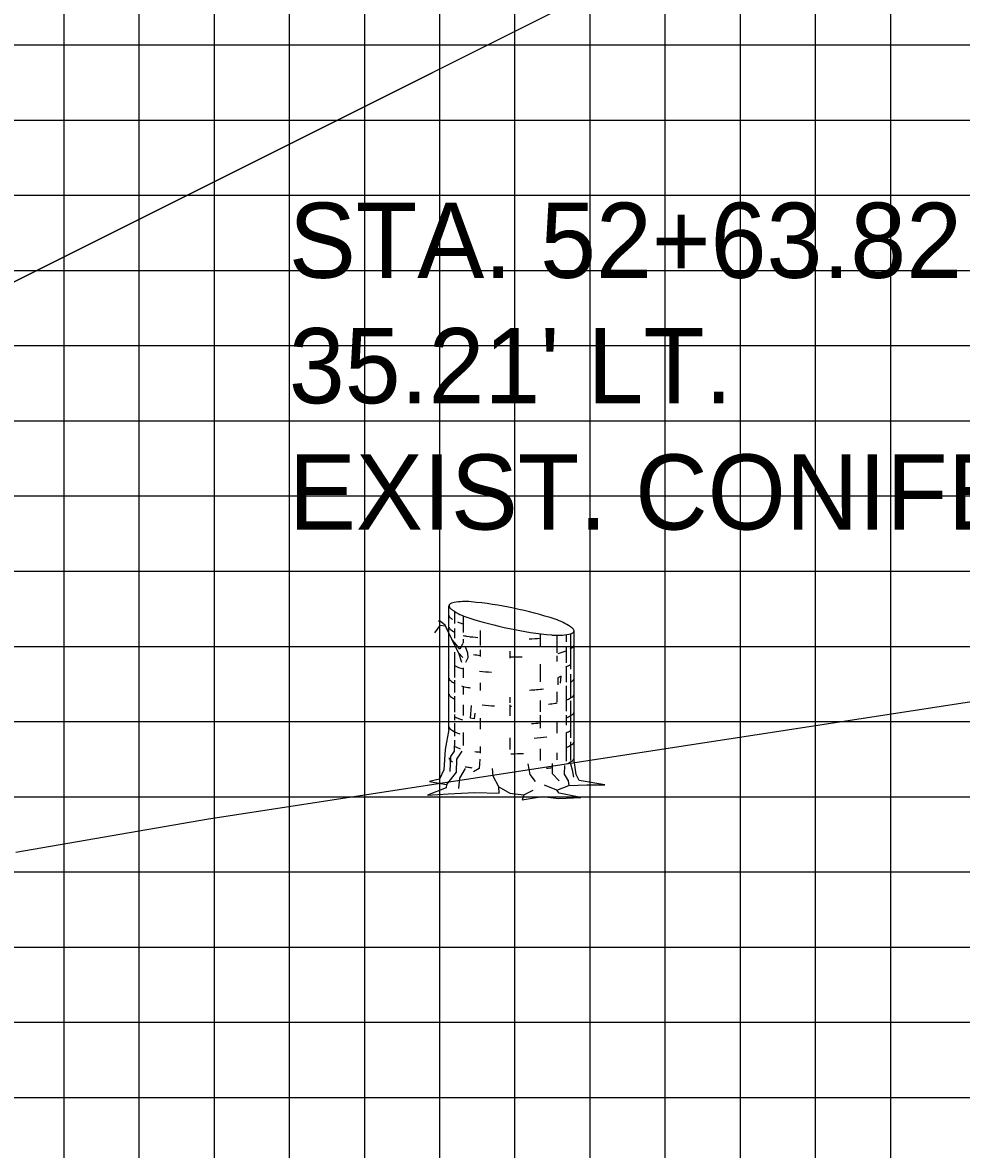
# Model space of a CAD drawing. Extents: x 1755888 to 1756232, y 442591 to 442811.
# Drawn here: x 1756011.5 to 1756024, y 442675.97 to 442690.96 of the extents above; entities that cross this region are included whole.
import ezdxf

# ---------------------------------------------------------------- set-up
doc = ezdxf.new("R2010")
doc.units = 0
for name, color, linetype in [('D_Roadway_Centerline', 7, 'Continuous'), ('D_Roadway_SlopeLines', 7, 'Continuous'), ('D_Text_Monospaced', 7, 'Continuous'), ('M_Trees_Conifer_Pay', 7, 'Continuous'), ('MAJOR', 7, 'Continuous'), ('MINOR', 7, 'Continuous'), ('S_Roadway_Centerline', 7, 'Continuous')]:
    doc.layers.add(name, color=color, linetype=linetype)

msp = doc.modelspace()

# ---------------------------------------------------------------- linework, layer by layer
at = {"layer": 'D_Roadway_Centerline'}
msp.add_lwpolyline([(1755988.922, 442676.281), (1756026.307, 442694.973), (1756031.057, 442697.348), (1756034.057, 442697.468), (1756042.057, 442697.788), (1756054.057, 442698.028), (1756066.057, 442697.788), (1756078.057, 442697.314), (1756093.723, 442696.688), (1756103.154, 442694.068), (1756119.307, 442689.581)], dxfattribs=at)
at = {"layer": 'D_Roadway_SlopeLines'}
msp.add_lwpolyline([(1756031.057, 442697.348), (1755988.922, 442676.281)], dxfattribs=at)
at = {"layer": 'M_Trees_Conifer_Pay'}
for p, q in [((1756017.179, 442681.557), (1756017.179, 442683.204)), ((1756017.251, 442683.132), (1756017.251, 442682.969)), ((1756017.368, 442683.071), (1756017.368, 442682.848)), ((1756017.251, 442682.902), (1756017.251, 442682.774)), ((1756017.596, 442682.875), (1756017.596, 442682.675)), ((1756017.368, 442682.759), (1756017.368, 442682.712)), ((1756018.392, 442682.833), (1756018.392, 442682.665)), ((1756018.612, 442682.813), (1756018.612, 442682.58)), ((1756018.737, 442682.82), (1756018.737, 442682.723)), ((1756018.796, 442682.832), (1756018.796, 442682.36)), ((1756018.843, 442681.147), (1756018.843, 442682.869)), ((1756017.251, 442682.587), (1756017.251, 442682.251)), ((1756017.311, 442682.576), (1756017.362, 442682.517)), ((1756017.596, 442682.618), (1756017.596, 442682.529)), ((1756017.987, 442682.601), (1756017.987, 442682.506)), ((1756018.737, 442682.648), (1756018.737, 442682.444)), ((1756018.392, 442682.428), (1756018.392, 442682.191)), ((1756018.612, 442682.54), (1756018.612, 442682.465)), ((1756017.368, 442682.377), (1756017.368, 442682.245)), ((1756018.737, 442682.387), (1756018.737, 442682.187)), ((1756018.796, 442682.296), (1756018.796, 442681.988)), ((1756017.251, 442682.214), (1756017.251, 442682.051)), ((1756017.368, 442682.134), (1756017.368, 442682.024)), ((1756017.596, 442682.181), (1756017.596, 442682.076)), ((1756018.737, 442682.14), (1756018.737, 442681.804)), ((1756017.251, 442682.004), (1756017.251, 442681.788)), ((1756017.987, 442681.988), (1756017.987, 442681.914)), ((1756018.612, 442682.062), (1756018.612, 442681.923)), ((1756017.368, 442681.889), (1756017.368, 442681.747)), ((1756017.987, 442681.889), (1756017.987, 442681.74)), ((1756018.392, 442681.946), (1756018.392, 442681.794)), ((1756018.796, 442681.94), (1756018.796, 442681.448)), ((1756017.251, 442681.757), (1756017.251, 442681.683)), ((1756017.596, 442681.709), (1756017.596, 442681.563)), ((1756018.392, 442681.751), (1756018.392, 442681.578)), ((1756018.737, 442681.751), (1756018.737, 442681.615)), ((1756017.251, 442681.642), (1756017.251, 442681.469)), ((1756018.612, 442681.652), (1756018.612, 442681.51)), ((1756017.368, 442681.52), (1756017.368, 442681.347)), ((1756017.987, 442681.448), (1756017.987, 442681.295)), ((1756018.737, 442681.516), (1756018.737, 442681.137)), ((1756018.796, 442681.395), (1756018.796, 442681.147)), ((1756017.596, 442681.331), (1756017.596, 442681.242)), ((1756018.392, 442681.3), (1756018.392, 442681.147)), ((1756018.612, 442681.248), (1756018.612, 442681.154)), ((1756018.612, 442680.754), (1756018.449, 442680.818)), ((1756018.175, 442680.69), (1756018.301, 442680.754))]:
    msp.add_line(p, q, dxfattribs=at)
for points in [[(1756017.133, 442682.935), (1756017.058, 442682.943), (1756016.985, 442682.844)], [(1756017.362, 442682.702), (1756017.325, 442682.628), (1756017.278, 442682.685), (1756017.22, 442682.753), (1756017.128, 442682.947), (1756017.064, 442682.994), (1756017.033, 442683.001)], [(1756017.348, 442682.449), (1756017.311, 442682.576), (1756017.247, 442682.692), (1756017.216, 442682.759), (1756017.148, 442682.906)], [(1756017.396, 442682.665), (1756017.426, 442682.58), (1756017.43, 442682.513), (1756017.4, 442682.449)], [(1756018.664, 442682.175), (1756018.67, 442682.27), (1756018.627, 442682.247), (1756018.627, 442682.152)], [(1756017.525, 442681.776), (1756017.512, 442681.699), (1756017.465, 442681.709), (1756017.478, 442681.876)], [(1756017.179, 442681.557), (1756017.128, 442681.295), (1756017.111, 442681.022), (1756017.054, 442680.897), (1756016.918, 442680.866), (1756017.148, 442680.828), (1756017.148, 442680.828), (1756017.142, 442680.781), (1756016.895, 442680.687), (1756017.169, 442680.703), (1756017.525, 442680.723), (1756017.846, 442680.713), (1756017.84, 442680.795), (1756017.988, 442680.713), (1756018.175, 442680.69), (1756018.151, 442680.622), (1756018.419, 442680.666), (1756018.639, 442680.639), (1756018.932, 442680.656), (1756018.643, 442680.713), (1756018.612, 442680.754), (1756018.775, 442680.812), (1756019.012, 442680.822), (1756019.253, 442680.822), (1756018.911, 442680.88), (1756018.869, 442680.96), (1756018.843, 442681.147)], [(1756017.253, 442681.415), (1756017.247, 442681.269), (1756017.2, 442681.201), (1756017.19, 442681.001)], [(1756017.352, 442681.269), (1756017.278, 442681.164), (1756017.274, 442680.991), (1756017.148, 442680.828)], [(1756017.589, 442681.164), (1756017.579, 442681.038), (1756017.505, 442680.995)], [(1756018.328, 442680.866), (1756018.26, 442680.96), (1756018.234, 442681.1)], [(1756018.554, 442681.106), (1756018.554, 442680.975), (1756018.643, 442680.876)], [(1756018.717, 442681.08), (1756018.711, 442680.964), (1756018.764, 442680.876), (1756018.775, 442680.812)], [(1756018.795, 442681.1), (1756018.816, 442681.022), (1756018.837, 442680.927)], [(1756017.311, 442680.775), (1756017.325, 442680.913), (1756017.4, 442681.042)], [(1756017.84, 442680.795), (1756017.766, 442680.937), (1756017.756, 442681.038)]]:
    msp.add_lwpolyline(points, dxfattribs=at)
for centre, radius, start, end in [((1756017.202, 442683.204), 0.0226, 156.5926, 168.2806), ((1756017.202, 442683.204), 0.0226, 168.2806, 179.9685), ((1756017.205, 442683.204), 0.0264, 179.9685, 190.7806), ((1756017.21, 442683.205), 0.0314, 190.7806, 203.4842), ((1756017.205, 442683.203), 0.0264, 145.7806, 156.5926), ((1756017.23, 442683.214), 0.0527, 203.4842, 213.2806), ((1756017.209, 442683.2), 0.0314, 133.077, 145.7806), ((1756017.254, 442683.23), 0.0817, 213.2806, 227.6113), ((1756017.224, 442683.185), 0.0527, 123.2806, 133.077), ((1756017.24, 442683.16), 0.0817, 108.9499, 123.2806), ((1756017.295, 442683.001), 0.251, 100.7806, 108.9499), ((1756017.398, 442682.459), 0.802, 84.6206, 100.7806), ((1756016.987, 442678.101), 5.179, 78.2806, 84.6206), ((1756016.987, 442678.101), 5.179, 71.9406, 78.2806), ((1756017.212, 442683.078), 0.0334, 185.7849, 196.0515), ((1756017.222, 442683.081), 0.0441, 196.0515, 210), ((1756017.238, 442683.09), 0.0624, 210, 228.7494), ((1756017.311, 442683.173), 0.172, 228.7494, 240), ((1756017.368, 442683.355), 0.251, 227.6113, 235.7806), ((1756017.678, 442683.81), 0.802, 235.7806, 251.9406), ((1756019.035, 442687.972), 5.179, 251.9406, 258.2806), ((1756018.344, 442682.263), 0.802, 55.7806, 71.9406), ((1756017.212, 442682.924), 0.0334, 185.7849, 196.0515), ((1756017.222, 442682.927), 0.0441, 196.0515, 210), ((1756017.238, 442682.936), 0.0624, 210, 228.7494), ((1756017.311, 442683.018), 0.172, 228.7494, 240), ((1756017.51, 442683.518), 0.571, 247.5868, 255.5683), ((1756019.035, 442687.972), 5.179, 258.2806, 264.6206), ((1756018.654, 442682.719), 0.251, 47.6113, 55.7806), ((1756018.768, 442682.843), 0.0817, 33.2806, 47.6113), ((1756018.792, 442682.859), 0.0527, 23.4842, 33.2806), ((1756018.812, 442682.868), 0.0314, 10.7806, 23.4842), ((1756018.817, 442682.869), 0.0264, 359.9685, 10.7806), ((1756017.51, 442683.363), 0.571, 240, 242.9763), ((1756017.51, 442683.363), 0.571, 255.6333, 261.8968), ((1756018.011, 442686.881), 4.124, 261.8968, 263.762), ((1756018.011, 442686.881), 4.124, 273.2669, 275.3045), ((1756018.624, 442683.614), 0.802, 264.6206, 280.7806), ((1756018.727, 442683.072), 0.251, 280.7806, 288.9499), ((1756018.782, 442682.913), 0.0817, 288.9499, 303.2806), ((1756018.798, 442682.889), 0.0527, 303.2806, 313.077), ((1756018.813, 442682.873), 0.0314, 313.077, 325.7806), ((1756018.817, 442682.87), 0.0264, 325.7806, 336.5926), ((1756018.82, 442682.869), 0.0226, 336.5926, 348.2806), ((1756018.82, 442682.869), 0.0226, 348.2806, 359.9685), ((1756018.513, 442683.13), 0.571, 282.0154, 293.1403), ((1756018.513, 442683.13), 0.571, 299.6633, 300), ((1756018.712, 442682.785), 0.172, 300, 311.2506), ((1756018.785, 442682.703), 0.0624, 311.2506, 330), ((1756018.801, 442682.694), 0.0441, 330, 343.9485), ((1756018.811, 442682.691), 0.0334, 0, 16.0515), ((1756018.811, 442682.691), 0.0334, 343.9485, 360), ((1756017.212, 442682.48), 0.0334, 185.7849, 196.0515), ((1756018.012, 442686.648), 4.124, 262.9442, 264.2151), ((1756018.012, 442686.648), 4.124, 269.6419, 270), ((1756018.012, 442686.648), 4.124, 270, 271.9249), ((1756018.512, 442682.919), 0.571, 292.9413, 300), ((1756017.51, 442682.919), 0.571, 242.9571, 255.5507), ((1756018.011, 442686.437), 4.124, 264.0496, 266.2948), ((1756017.214, 442682.244), 0.0334, 185.7849, 196.0515), ((1756017.224, 442682.247), 0.0441, 196.0515, 210), ((1756017.24, 442682.256), 0.0624, 210, 228.7494), ((1756017.312, 442682.339), 0.172, 228.7494, 240), ((1756017.511, 442682.684), 0.571, 240, 242.8104), ((1756017.511, 442682.684), 0.571, 253.0704, 261.8968), ((1756018.513, 442682.684), 0.571, 299.6633, 300), ((1756018.712, 442682.339), 0.172, 300, 311.2506), ((1756018.785, 442682.256), 0.0624, 311.2506, 330), ((1756018.801, 442682.247), 0.0441, 330, 343.9485), ((1756018.811, 442682.244), 0.0334, 0, 16.0515), ((1756018.811, 442682.244), 0.0334, 343.9485, 360), ((1756017.214, 442682.034), 0.0334, 185.7849, 196.0515), ((1756017.224, 442682.037), 0.0441, 196.0515, 210), ((1756017.24, 442682.046), 0.0624, 210, 228.7494), ((1756017.312, 442682.129), 0.172, 228.7494, 240), ((1756017.511, 442682.474), 0.571, 240, 242.8104), ((1756018.012, 442686.201), 4.124, 261.8968, 262.3875), ((1756018.012, 442686.201), 4.124, 273.3324, 275.919), ((1756018.513, 442682.474), 0.571, 293.1403, 300), ((1756018.712, 442682.129), 0.172, 300, 311.2506), ((1756018.785, 442682.046), 0.0624, 311.2506, 330), ((1756018.801, 442682.037), 0.0441, 330, 343.9485), ((1756018.811, 442682.034), 0.0334, 0, 16.0515), ((1756018.811, 442682.034), 0.0334, 343.9485, 360), ((1756018.012, 442685.991), 4.124, 264.5431, 266.8507), ((1756018.012, 442685.991), 4.124, 269.6419, 270), ((1756018.012, 442685.991), 4.124, 276.8526, 278.1032), ((1756018.513, 442682.474), 0.571, 278.1032, 280.7293), ((1756017.511, 442682.237), 0.571, 242.8104, 254.6017), ((1756018.513, 442682.237), 0.571, 293.1403, 300), ((1756018.712, 442681.892), 0.172, 300, 311.2506), ((1756018.785, 442681.809), 0.0624, 311.2506, 330), ((1756018.801, 442681.8), 0.0441, 330, 343.9485), ((1756018.811, 442681.797), 0.0334, 0, 16.0515), ((1756018.811, 442681.797), 0.0334, 343.9485, 360), ((1756017.214, 442681.599), 0.0334, 185.7849, 196.0515), ((1756017.224, 442681.602), 0.0441, 196.0515, 210), ((1756017.24, 442681.612), 0.0624, 210, 228.7494), ((1756017.312, 442681.694), 0.172, 228.7494, 240), ((1756017.511, 442682.039), 0.571, 240, 250.7093), ((1756018.012, 442685.754), 4.124, 273.6807, 275.284), ((1756018.524, 442682.045), 0.571, 291.9732, 298.7631), ((1756018.811, 442681.599), 0.0334, 0, 16.0515), ((1756018.012, 442685.557), 4.124, 274.1603, 276.5009), ((1756018.785, 442681.416), 0.0624, 311.2506, 330), ((1756018.801, 442681.407), 0.0441, 330, 343.9485), ((1756018.811, 442681.404), 0.0334, 0, 16.0515), ((1756018.811, 442681.404), 0.0334, 343.9485, 360), ((1756017.511, 442681.844), 0.571, 242.7279, 251.4933), ((1756018.012, 442685.361), 4.124, 263.2104, 264.2151), ((1756018.012, 442685.361), 4.124, 269.8672, 270), ((1756018.012, 442685.361), 4.124, 270, 272.1883), ((1756018.513, 442681.844), 0.571, 293.1403, 300), ((1756018.712, 442681.499), 0.172, 300, 311.2506), ((1756017.214, 442681.184), 0.0334, 185.7849, 196.0515), ((1756017.224, 442681.186), 0.0441, 196.0515, 210), ((1756017.24, 442681.196), 0.0624, 210, 228.7494), ((1756017.312, 442681.278), 0.172, 228.7494, 240), ((1756018.513, 442681.623), 0.571, 295.4686, 300), ((1756018.712, 442681.278), 0.172, 300, 311.2506), ((1756018.785, 442681.196), 0.0624, 311.2506, 330), ((1756018.801, 442681.186), 0.0441, 330, 343.9485), ((1756018.811, 442681.184), 0.0334, 0, 16.0515), ((1756018.811, 442681.184), 0.0334, 343.9485, 360), ((1756017.511, 442681.623), 0.571, 258.363, 261.8968), ((1756018.012, 442685.141), 4.124, 261.8968, 262.6316), ((1756018.012, 442685.141), 4.124, 276.488, 277.5562)]:
    msp.add_arc(centre, radius, start, end, dxfattribs=at)
at = {"layer": 'MAJOR'}
for p, q in [((1756014.057, 442668.665), (1756014.057, 442703.665)), ((1755914.057, 442688.665), (1756194.057, 442688.665)), ((1755914.057, 442683.665), (1756194.057, 442683.665)), ((1755914.057, 442678.665), (1756194.057, 442678.665))]:
    msp.add_line(p, q, dxfattribs=at)
at = {"layer": 'MINOR'}
for p, q in [((1756012.057, 442668.665), (1756012.057, 442703.665)), ((1756013.057, 442668.665), (1756013.057, 442703.665)), ((1756015.057, 442668.665), (1756015.057, 442703.665)), ((1756016.057, 442668.665), (1756016.057, 442703.665)), ((1756017.057, 442668.665), (1756017.057, 442703.665)), ((1756018.057, 442668.665), (1756018.057, 442703.665)), ((1756019.057, 442668.665), (1756019.057, 442703.665)), ((1756020.057, 442668.665), (1756020.057, 442703.665)), ((1756021.057, 442668.665), (1756021.057, 442703.665)), ((1756022.057, 442668.665), (1756022.057, 442703.665)), ((1756023.057, 442668.665), (1756023.057, 442703.665)), ((1755914.057, 442690.665), (1756194.057, 442690.665)), ((1755914.057, 442689.665), (1756194.057, 442689.665)), ((1755914.057, 442687.665), (1756194.057, 442687.665)), ((1755914.057, 442686.665), (1756194.057, 442686.665)), ((1755914.057, 442685.665), (1756194.057, 442685.665)), ((1755914.057, 442684.665), (1756194.057, 442684.665)), ((1755914.057, 442682.665), (1756194.057, 442682.665)), ((1755914.057, 442681.665), (1756194.057, 442681.665)), ((1755914.057, 442680.665), (1756194.057, 442680.665)), ((1755914.057, 442679.665), (1756194.057, 442679.665)), ((1755914.057, 442677.665), (1756194.057, 442677.665)), ((1755914.057, 442676.665), (1756194.057, 442676.665))]:
    msp.add_line(p, q, dxfattribs=at)
at = {"layer": 'S_Roadway_Centerline'}
msp.add_lwpolyline([(1756011.415, 442679.926), (1756013.978, 442680.371), (1756038.592, 442684.155), (1756041.872, 442684.674), (1756042.879, 442684.708), (1756044.461, 442684.799), (1756060.284, 442685.471), (1756075.572, 442688.669), (1756079.705, 442689.201), (1756081.969, 442689.651), (1756090.362, 442690.015), (1756099.67, 442689.942), (1756106.379, 442690.09), (1756121.311, 442689.502), (1756138.054, 442689.488), (1756139.019, 442689.391), (1756142.385, 442688.795), (1756158.924, 442685.483), (1756163.121, 442684.674), (1756170.029, 442683.558), (1756174.253, 442682.817), (1756177.852, 442682.58), (1756191.592, 442681.484), (1756194.057, 442681.352)], dxfattribs=at)

# ---------------------------------------------------------------- texts
at = {"layer": 'D_Text_Monospaced'}
for s, height, p in [('STA. 52+63.82', 0.99996, (1756015.048, 442687.566)), ("35.21' LT.", 1, (1756015.048, 442685.898)), ('EXIST. CONIFER', 0.99996, (1756015.048, 442684.218))]:
    msp.add_text(s, height=height, dxfattribs=at).set_placement(p)

doc.saveas('drawing.dxf')
